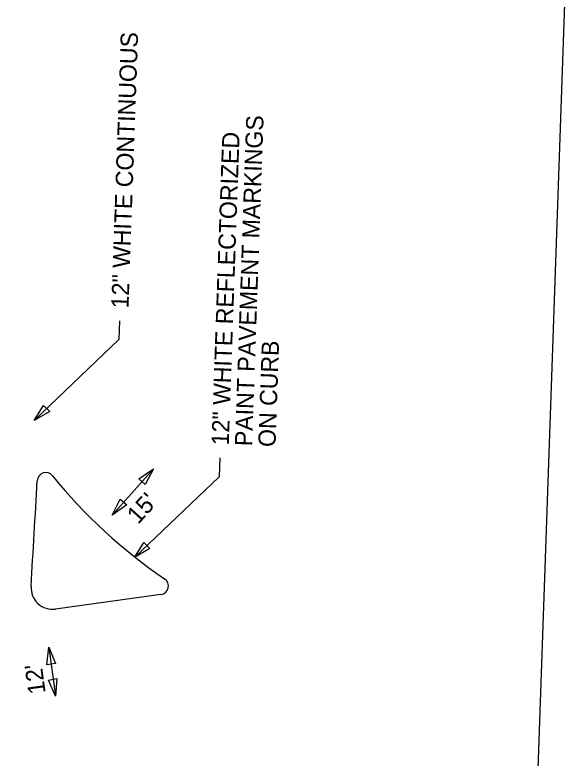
# Model space of a CAD drawing. Extents: x 633912 to 634995, y 289794 to 291427.
# Drawn here: x 634621.6 to 634813.8, y 291002.9 to 291261.1 of the extents above; entities that cross this region are included whole.
import ezdxf

# ---------------------------------------------------------------- set-up
doc = ezdxf.new("R2010")
doc.units = 0
for name, color, linetype in [('B_Concrete', 7, 'Continuous'), ('R_Dimension', 7, 'Continuous'), ('R_Striping', 7, 'Continuous'), ('ROAD', 7, 'Continuous')]:
    doc.layers.add(name, color=color, linetype=linetype)

msp = doc.modelspace()

# ---------------------------------------------------------------- linework, layer by layer
at = {"layer": 'B_Concrete'}
msp.add_line((634672.34, 291059.76), (634635.72, 291054.7), dxfattribs=at)
for centre, radius, start, end in [((634632.33, 291099.14), 3, 38.8783, 176.7333), ((617429.6, 292081.01), 17227.73, 356.61091, 356.733292), ((634773.63, 291213.06), 178.5, 218.8783, 235.9205), ((634671.93, 291062.73), 3, 277.8642, 55.9205), ((634634.69, 291062.13), 7.5, 176.6109, 277.8642)]:
    msp.add_arc(centre, radius, start, end, dxfattribs=at)
at = {"layer": 'R_Dimension'}
for points in [[(634633.66, 291123.3), (634628.31, 291120.2), (634631.57, 291125.46)], [(634664.64, 291099.94), (634669.78, 291103.38), (634666.86, 291097.93)], [(634660.45, 291090.88), (634655.35, 291087.37), (634658.2, 291092.86)], [(634668.49, 291075.71), (634663.14, 291072.6), (634666.4, 291077.86)], [(634632.73, 291035.36), (634633.38, 291041.51), (634635.71, 291035.78)], [(634636.19, 291030.59), (634635.74, 291024.42), (634633.24, 291030.07)]]:
    msp.add_lwpolyline(points, close=True, dxfattribs=at)
at = {"layer": 'R_Striping'}
msp.add_lwpolyline([(634473.68, 290807.74), (634491.32, 291312.97), (634813.84, 291301.71), (634796.19, 290796.48)], close=True, dxfattribs=at)
at = {"layer": 'ROAD'}
for p, q in [((634655.35, 291087.37), (634669.78, 291103.38)), ((634633.38, 291041.51), (634635.74, 291024.42))]:
    msp.add_line(p, q, dxfattribs=at)
for points in [[(634657.98, 291154.8), (634657.75, 291148.3), (634628.31, 291120.2)], [(634692.8, 291107.21), (634692.58, 291100.7), (634663.14, 291072.6)]]:
    msp.add_lwpolyline(points, dxfattribs=at)

# ---------------------------------------------------------------- texts
for s, rotation, p in [('12" WHITE CONTINUOUS', 88, (634661.05, 291159.09)), ('PAINT PAVEMENT MARKINGS', 88, (634704, 291111.21)), ('12" WHITE REFLECTORIZED', 88, (634695.88, 291111.49)), ('ON CURB', 88, (634712.12, 291110.92)), ("15'", 47.977, (634664.41, 291083.91)), ("12'", 97.8642, (634632.28, 291025.57))]:
    msp.add_text(s, height=6, rotation=rotation, dxfattribs=at).set_placement(p)

doc.saveas('drawing.dxf')
